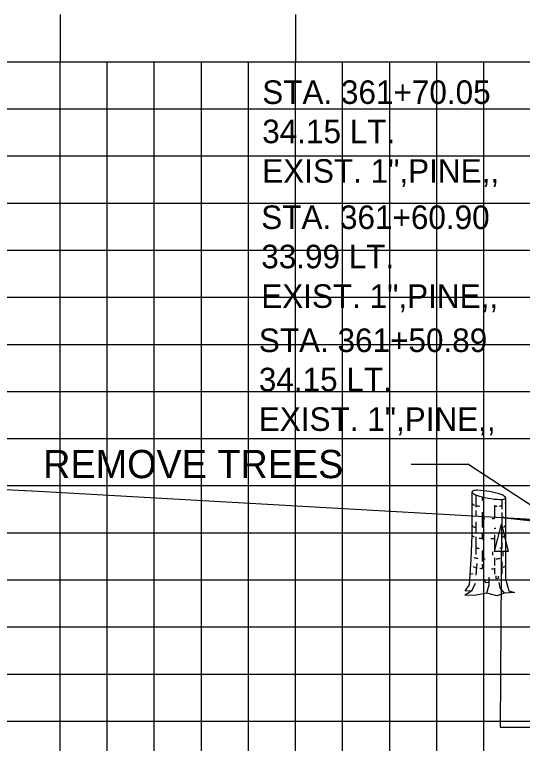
# Model space of a CAD drawing. Extents: x 1146525 to 1146695, y 608981 to 609091.
# Drawn here: x 1146561.7 to 1146572.49, y 609060.86 to 609076.34 of the extents above; entities that cross this region are included whole.
import ezdxf

# ---------------------------------------------------------------- set-up
doc = ezdxf.new("R2010")
doc.units = 0
for name, color, linetype in [('ANNOTATION', 7, 'Continuous'), ('D_Roadway_SlopeLines', 7, 'Continuous'), ('D_Text_Monospaced', 7, 'Continuous'), ('D_Text_Standard', 7, 'Continuous'), ('MAJOR', 7, 'Continuous'), ('MINOR', 7, 'Continuous'), ('S_Roadway_Centerline', 7, 'Continuous'), ('S_Trees_Conifer_NonPay', 7, 'Continuous')]:
    doc.layers.add(name, color=color, linetype=linetype)

msp = doc.modelspace()

# ---------------------------------------------------------------- linework, layer by layer
msp.add_lwpolyline([(1146572.045, 609065.661), (1146573.295, 609065.521), (1146574.545, 609065.242), (1146575.795, 609064.824), (1146577.045, 609064.269), (1146581.947, 609061.818), (1146584.947, 609062.818), (1146592.67, 609065.392), (1146592.671, 609065.392), (1146596.671, 609065.552), (1146607.671, 609065.772), (1146618.671, 609065.552), (1146622.671, 609065.392), (1146630.395, 609062.818), (1146633.395, 609061.818), (1146643.18, 609066.71), (1146644.43, 609067.259), (1146645.68, 609067.654), (1146646.93, 609067.897), (1146648.18, 609067.986)])
at = {"layer": 'ANNOTATION'}
for p in [(1146570.129, 609066.794), (1146573.678, 609065.258)]:
    msp.add_line(p, (1146571.329, 609066.794), dxfattribs=at)
at = {"layer": 'D_Roadway_SlopeLines'}
msp.add_lwpolyline([(1146581.947, 609061.818), (1146577.045, 609064.269), (1146575.795, 609064.824), (1146574.545, 609065.242), (1146573.295, 609065.521), (1146572.045, 609065.661)], dxfattribs=at)
at = {"layer": 'D_Text_Standard'}
msp.add_lwpolyline([(1146572.045, 609065.519), (1146572.187, 609064.936), (1146571.896, 609064.937)], close=True, dxfattribs=at)
msp.add_lwpolyline([(1146572.045, 609065.519), (1146572.02, 609061.207), (1146572.7, 609061.207)], dxfattribs=at)
at = {"layer": 'MAJOR'}
for p, q in [((1146562.671, 609076.337), (1146562.671, 609075.335)), ((1146567.671, 609076.337), (1146567.671, 609075.335)), ((1146537.671, 609075.335), (1146677.671, 609075.335)), ((1146537.671, 609075.335), (1146677.671, 609075.335)), ((1146562.671, 609055.335), (1146562.671, 609075.335)), ((1146567.671, 609055.335), (1146567.671, 609075.335)), ((1146537.671, 609070.335), (1146677.671, 609070.335)), ((1146537.671, 609065.335), (1146677.671, 609065.335))]:
    msp.add_line(p, q, dxfattribs=at)
at = {"layer": 'MINOR'}
for p, q in [((1146563.671, 609055.335), (1146563.671, 609075.335)), ((1146564.671, 609055.335), (1146564.671, 609075.335)), ((1146565.671, 609055.335), (1146565.671, 609075.335)), ((1146566.671, 609055.335), (1146566.671, 609075.335)), ((1146568.671, 609055.335), (1146568.671, 609075.335)), ((1146569.671, 609055.335), (1146569.671, 609075.335)), ((1146570.671, 609055.335), (1146570.671, 609075.335)), ((1146571.671, 609055.335), (1146571.671, 609075.335)), ((1146537.671, 609074.335), (1146677.671, 609074.335)), ((1146537.671, 609073.335), (1146677.671, 609073.335)), ((1146537.671, 609072.335), (1146677.671, 609072.335)), ((1146537.671, 609071.335), (1146677.671, 609071.335)), ((1146537.671, 609069.335), (1146677.671, 609069.335)), ((1146537.671, 609068.335), (1146677.671, 609068.335)), ((1146537.671, 609067.335), (1146677.671, 609067.335)), ((1146537.671, 609066.335), (1146677.671, 609066.335)), ((1146537.671, 609064.335), (1146677.671, 609064.335)), ((1146537.671, 609063.335), (1146677.671, 609063.335)), ((1146537.671, 609062.335), (1146677.671, 609062.335)), ((1146537.671, 609061.335), (1146677.671, 609061.335))]:
    msp.add_line(p, q, dxfattribs=at)
at = {"layer": 'S_Roadway_Centerline'}
msp.add_lwpolyline([(1146555.658, 609066.541), (1146562.215, 609066.221), (1146582.411, 609065.07), (1146583.316, 609064.912), (1146587.853, 609063.497), (1146588.571, 609063.642), (1146593.356, 609064.948), (1146593.601, 609064.956), (1146595.56, 609064.969), (1146601.488, 609065.115), (1146606.926, 609065.194), (1146612.815, 609065.044), (1146617.656, 609064.926), (1146621.703, 609064.693), (1146621.82, 609064.681), (1146621.879, 609064.655), (1146624.765, 609063.492), (1146625.761, 609063.915), (1146635.495, 609067.854), (1146654.514, 609068.052), (1146655.612, 609068.025)], dxfattribs=at)
at = {"layer": 'S_Trees_Conifer_NonPay'}
for p, q in [((1146571.636, 609066.097), (1146571.636, 609066.019)), ((1146572.054, 609066.042), (1146572.054, 609065.837)), ((1146571.501, 609065.809), (1146571.501, 609065.678)), ((1146571.898, 609065.918), (1146571.898, 609065.644)), ((1146571.636, 609065.769), (1146571.636, 609065.444)), ((1146572.054, 609065.764), (1146572.054, 609065.433)), ((1146571.501, 609065.569), (1146571.501, 609065.343)), ((1146571.636, 609065.343), (1146571.636, 609065.189)), ((1146572.054, 609065.319), (1146572.054, 609065.24)), ((1146571.501, 609065.251), (1146571.501, 609064.875)), ((1146571.898, 609065.29), (1146571.898, 609064.972)), ((1146572.054, 609065.126), (1146572.054, 609065.016)), ((1146571.636, 609064.961), (1146571.636, 609064.727)), ((1146571.856, 609064.927), (1146571.856, 609064.858)), ((1146572.071, 609064.939), (1146572.071, 609064.841)), ((1146571.898, 609064.802), (1146571.898, 609064.643)), ((1146572.054, 609064.727), (1146572.054, 609064.46)), ((1146571.52, 609064.682), (1146571.503, 609064.437)), ((1146571.636, 609064.665), (1146571.636, 609064.579)), ((1146571.898, 609064.585), (1146571.898, 609064.454)), ((1146571.441, 609064.454), (1146571.38, 609064.46))]:
    msp.add_line(p, q, dxfattribs=at)
for points in [[(1146571.39, 609064.093), (1146571.274, 609064.102), (1146571.366, 609064.227), (1146571.4, 609064.768), (1146571.42, 609065.285), (1146571.42, 609066.204)], [(1146571.501, 609066.138), (1146571.501, 609066.041), (1146571.501, 609065.876)], [(1146572.133, 609066.076), (1146572.133, 609064.359), (1146572.203, 609064.102), (1146572.322, 609064.068), (1146572.106, 609064.051), (1146571.946, 609063.993), (1146571.737, 609064.051), (1146571.474, 609064.004), (1146571.268, 609064.01), (1146571.42, 609064.113), (1146571.491, 609064.267)], [(1146571.737, 609064.051), (1146571.781, 609064.227), (1146571.787, 609064.392)], [(1146571.974, 609064.414), (1146571.985, 609064.37), (1146571.935, 609064.359), (1146571.935, 609064.42)], [(1146571.783, 609064.277), (1146571.714, 609064.272), (1146571.695, 609064.324)], [(1146572.106, 609064.051), (1146572.016, 609064.164), (1146571.999, 609064.278)]]:
    msp.add_lwpolyline(points, dxfattribs=at)
for centre, radius, start, end in [((1146571.434, 609066.202), 0.0141, 153.567, 169.6202), ((1146571.434, 609066.202), 0.0141, 169.6202, 185.6733), ((1146571.439, 609066.202), 0.0186, 185.6733, 199.6202), ((1146571.446, 609066.205), 0.0263, 199.6202, 218.3805), ((1146571.438, 609066.2), 0.0186, 139.6202, 153.567), ((1146571.444, 609066.195), 0.0263, 120.8598, 139.6202), ((1146571.482, 609066.234), 0.0729, 218.3805, 229.6202), ((1146571.468, 609066.155), 0.0729, 109.6202, 120.8598), ((1146571.594, 609066.365), 0.245, 229.6202, 251.6054), ((1146571.526, 609065.993), 0.245, 87.6349, 109.6202), ((1146572.093, 609067.865), 1.825, 251.6054, 259.6202), ((1146571.461, 609064.414), 1.825, 79.6202, 87.6349), ((1146571.461, 609064.414), 1.825, 71.6054, 79.6202), ((1146571.959, 609065.913), 0.245, 49.6202, 71.6054), ((1146572.071, 609066.045), 0.0729, 38.3805, 49.6202), ((1146572.107, 609066.073), 0.0263, 19.6202, 38.3805), ((1146571.438, 609065.962), 0.0189, 196.0515, 210), ((1146571.445, 609065.966), 0.0267, 210, 228.7494), ((1146571.476, 609066.001), 0.0738, 228.7494, 240), ((1146571.561, 609066.149), 0.245, 240, 248.2347), ((1146572.093, 609067.865), 1.825, 259.6202, 267.6349), ((1146572.027, 609066.286), 0.245, 267.6349, 289.6202), ((1146572.085, 609066.124), 0.0729, 289.6202, 300.8598), ((1146572.109, 609066.084), 0.0263, 300.8598, 319.6202), ((1146572.115, 609066.079), 0.0186, 319.6202, 333.567), ((1146572.115, 609066.076), 0.0186, 5.6733, 19.6202), ((1146572.119, 609066.077), 0.0141, 333.567, 349.6202), ((1146572.118, 609065.961), 0.0143, 343.9485, 360), ((1146572.119, 609066.077), 0.0141, 349.6202, 5.6733), ((1146571.561, 609066.149), 0.245, 255.8141, 261.8968), ((1146571.776, 609067.657), 1.767, 261.8968, 263.7551), ((1146571.776, 609067.657), 1.767, 273.9501, 275.6733), ((1146571.776, 609067.657), 1.767, 277.395, 278.1032), ((1146571.991, 609066.149), 0.245, 278.1032, 285.1539), ((1146571.436, 609065.71), 0.0189, 196.0515, 210), ((1146571.443, 609065.714), 0.0267, 210, 228.7494), ((1146571.774, 609067.405), 1.767, 265.5153, 267.2779), ((1146571.774, 609067.405), 1.767, 272.4038, 274.1009), ((1146571.989, 609065.897), 0.245, 282.4625, 295.6852), ((1146571.438, 609065.496), 0.0189, 196.0515, 210), ((1146571.445, 609065.5), 0.0267, 210, 228.7494), ((1146571.476, 609065.535), 0.0738, 228.7494, 240), ((1146571.561, 609065.683), 0.245, 240, 255.8141), ((1146571.991, 609065.683), 0.245, 293.2086, 300), ((1146572.076, 609065.535), 0.0738, 300, 311.2506), ((1146572.107, 609065.5), 0.0267, 311.2506, 330), ((1146572.114, 609065.496), 0.0189, 330, 343.9485), ((1146572.118, 609065.495), 0.0143, 343.9485, 360), ((1146571.776, 609067.191), 1.767, 273.8675, 274.7715), ((1146571.991, 609065.683), 0.245, 282.4546, 285.1539), ((1146571.438, 609065.285), 0.0189, 196.0515, 210), ((1146571.445, 609065.288), 0.0267, 210, 228.7494), ((1146571.476, 609065.324), 0.0738, 228.7494, 240), ((1146571.561, 609065.472), 0.245, 240, 247.8076), ((1146571.776, 609066.979), 1.767, 262.9974, 265.4639), ((1146571.776, 609066.979), 1.767, 271.4475, 273.9571), ((1146571.99, 609065.472), 0.245, 285.0486, 300), ((1146572.076, 609065.324), 0.0738, 300, 311.2506), ((1146572.107, 609065.288), 0.0267, 311.2506, 330), ((1146572.114, 609065.285), 0.0189, 330, 343.9485), ((1146572.118, 609065.283), 0.0143, 343.9485, 360), ((1146571.562, 609065.252), 0.245, 255.6793, 261.8968), ((1146571.777, 609066.76), 1.767, 261.8968, 263.2034), ((1146571.777, 609066.76), 1.767, 277.55, 278.1032), ((1146571.991, 609065.252), 0.245, 278.1032, 285.0186), ((1146572.119, 609064.847), 0.0143, 343.9485, 360), ((1146571.562, 609065.035), 0.245, 245.3944, 261.8968), ((1146571.777, 609066.543), 1.767, 261.8968, 262.37), ((1146571.777, 609066.543), 1.767, 265.4388, 267.3707), ((1146571.777, 609066.543), 1.767, 274.9504, 277.7378), ((1146571.477, 609064.682), 0.0738, 237.95, 240), ((1146571.563, 609064.83), 0.245, 240, 255.9316), ((1146571.777, 609066.337), 1.767, 263.6994, 265.7224), ((1146571.777, 609066.337), 1.767, 271.7813, 273.9138), ((1146571.992, 609064.83), 0.245, 290.8325, 300), ((1146572.077, 609064.682), 0.0738, 300, 311.2506), ((1146572.108, 609064.646), 0.0267, 311.2506, 330), ((1146572.115, 609064.642), 0.0189, 330, 343.9485), ((1146572.119, 609064.641), 0.0143, 343.9485, 360)]:
    msp.add_arc(centre, radius, start, end, dxfattribs=at)

# ---------------------------------------------------------------- texts
at = {"layer": 'ANNOTATION'}
msp.add_text('REMOVE TREES', height=0.6, dxfattribs=at).set_placement((1146562.311, 609066.494))
at = {"layer": 'D_Text_Monospaced'}
for s, height, p in [('STA. 361+70.05', 0.49998, (1146566.964, 609074.44)), ('34.15 LT.', 0.5, (1146566.964, 609073.606)), ('EXIST. 1",PINE,,', 0.49998, (1146566.964, 609072.766)), ('STA. 361+60.90', 0.49998, (1146566.943, 609071.784)), ('33.99 LT.', 0.5, (1146566.943, 609070.95)), ('EXIST. 1",PINE,,', 0.49998, (1146566.943, 609070.11)), ('STA. 361+50.89', 0.49998, (1146566.891, 609069.172)), ('34.15 LT.', 0.5, (1146566.891, 609068.338)), ('EXIST. 1",PINE,,', 0.49998, (1146566.891, 609067.498))]:
    msp.add_text(s, height=height, dxfattribs=at).set_placement(p)

doc.saveas('drawing.dxf')
